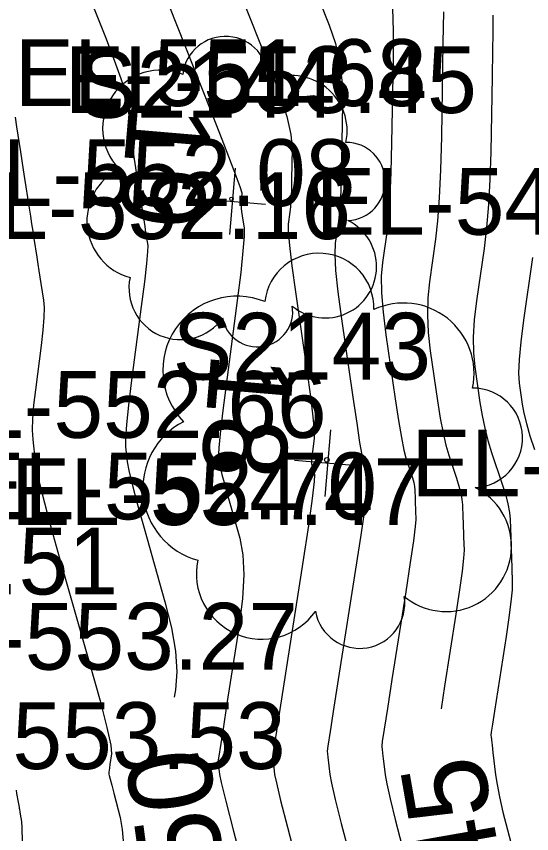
# Model space of a CAD drawing. Extents: x 1724534 to 1727318, y 657156 to 660047.
# Drawn here: x 1725483.91 to 1725514.76, y 658941.32 to 658990.26 of the extents above; entities that cross this region are included whole.
import ezdxf

# ---------------------------------------------------------------- set-up
doc = ezdxf.new("R2010")
doc.units = 0
for name, color, linetype in [('SURVEY - CENTERLINE - Preliminary', 7, 'Continuous'), ('SURVEY - CONTOURS - Index with Text', 7, 'Continuous'), ('SURVEY - CONTOURS - Intermediate with optional Text', 7, 'Continuous'), ('SURVEY - ROADSIDE BARRIERS - Points - Elevations', 7, 'Continuous'), ('SURVEY - TRAFFIC CONTROL - Pavement Marking - Points - Elevations', 7, 'Continuous'), ('SURVEY - TRANSPORTATION - Features - Points - Elevations', 7, 'Continuous'), ('SURVEY - TRANSPORTATION - Roads - Points - Elevations', 7, 'Continuous'), ('SURVEY - VEGETATION - Features - Points - Elevations', 7, 'Continuous'), ('SURVEY - VEGETATION - Features - Points - Locators', 7, 'Continuous'), ('SURVEY - VEGETATION - Features - Points - Numbers', 7, 'Continuous'), ('SURVEY - VEGETATION - Features with Text', 7, 'Continuous')]:
    doc.layers.add(name, color=color, linetype=linetype)

msp = doc.modelspace()

# ---------------------------------------------------------------- linework, layer by layer
at = {"layer": 'SURVEY - CENTERLINE - Preliminary'}
msp.add_arc((1727061.077, 658773.081), 1600, 165.79242, 172.785391, dxfattribs=at)
msp.add_arc((1727061.077, 658773.081), 1600, 165.79242, 172.785391, dxfattribs=at)
msp.add_arc((1727061.077, 658773.081), 1600, 165.79242, 172.785391, dxfattribs=at)
at = {"layer": 'SURVEY - CONTOURS - Index with Text'}
for points in [[(1725487.622, 658993.087), (1725489.235, 658989.013), (1725489.77, 658987.633), (1725490.164, 658986.548), (1725490.417, 658985.758), (1725490.53, 658985.263), (1725490.643, 658984.336), (1725490.684, 658983.995), (1725490.724, 658983.669), (1725490.763, 658983.355), (1725490.799, 658983.056), (1725490.895, 658982.275), (1725490.931, 658981.988), (1725490.968, 658981.71), (1725491.006, 658981.443), (1725491.045, 658981.186), (1725491.15, 658980.513), (1725491.188, 658980.266), (1725491.226, 658980.027), (1725491.262, 658979.797), (1725491.296, 658979.575), (1725491.386, 658978.997), (1725491.42, 658978.784), (1725491.452, 658978.578), (1725491.483, 658978.378), (1725491.513, 658978.186), (1725491.591, 658977.684), (1725491.62, 658977.498), (1725491.648, 658977.318), (1725491.675, 658977.144), (1725491.701, 658976.976), (1725491.77, 658976.535), (1725491.766, 658976.183), (1725491.701, 658975.459), (1725491.575, 658974.361), (1725491.389, 658972.89), (1725490.811, 658968.471), (1725490.626, 658966.979), (1725490.504, 658965.816), (1725490.446, 658964.983), (1725490.45, 658964.479), (1725490.545, 658963.575), (1725490.635, 658963.072), (1725490.833, 658962.243), (1725491.139, 658961.086), (1725491.554, 658959.602), (1725492.803, 658955.209), (1725493.193, 658953.644), (1725493.428, 658952.242), (1725493.507, 658951.005), (1725493.43, 658949.933), (1725493.362, 658949.5)], [(1725509.486, 658990.526), (1725509.454, 658988.673), (1725509.356, 658983.039), (1725509.306, 658981.071), (1725509.232, 658979.393), (1725509.133, 658978.006), (1725509.009, 658976.908), (1725508.644, 658974.369), (1725508.545, 658973.396), (1725508.521, 658972.381), (1725508.571, 658971.325), (1725508.696, 658970.228), (1725509.13, 658967.246), (1725509.294, 658966.203), (1725509.46, 658965.312), (1725509.629, 658964.572), (1725509.8, 658963.983), (1725510.258, 658962.614), (1725510.409, 658962.128), (1725510.52, 658961.699), (1725510.591, 658961.327), (1725510.621, 658961.011), (1725510.647, 658960.243), (1725510.657, 658959.954), (1725510.667, 658959.663), (1725510.677, 658959.37), (1725510.687, 658959.074), (1725510.713, 658958.285), (1725510.691, 658957.824), (1725510.602, 658957.033), (1725510.448, 658955.912), (1725510.229, 658954.46), (1725509.555, 658950.151), (1725509.343, 658948.791)]]:
    msp.add_lwpolyline(points, dxfattribs=at)
at = {"layer": 'SURVEY - CONTOURS - Intermediate with optional Text'}
for points in [[(1725501.52, 658992.574), (1725502.644, 658989.734), (1725503.01, 658988.641), (1725503.265, 658987.491), (1725503.409, 658986.284), (1725503.442, 658985.02), (1725503.382, 658981.574), (1725503.354, 658980.381), (1725503.313, 658979.387), (1725503.26, 658978.592), (1725503.195, 658977.995), (1725503.004, 658976.668), (1725502.974, 658976.013), (1725503.025, 658975.042), (1725503.158, 658973.756), (1725503.373, 658972.155), (1725504.056, 658967.464), (1725504.286, 658965.906), (1725504.465, 658964.75), (1725504.593, 658963.997), (1725504.668, 658963.646), (1725504.802, 658963.247), (1725504.846, 658963.106), (1725504.879, 658962.981), (1725504.899, 658962.872), (1725504.908, 658962.78), (1725504.918, 658962.472), (1725504.921, 658962.387), (1725504.927, 658962.215), (1725504.935, 658961.985), (1725504.892, 658961.618), (1725504.757, 658960.691), (1725504.531, 658959.201), (1725504.212, 658957.151), (1725503.241, 658950.936), (1725502.923, 658948.896), (1725502.696, 658947.437), (1725502.559, 658946.56), (1725502.514, 658946.264), (1725502.534, 658946.093), (1725502.557, 658945.906), (1725502.68, 658944.856), (1725502.779, 658944.334), (1725503.007, 658943.358), (1725503.364, 658941.93), (1725503.85, 658940.05)], [(1725497.279, 658991.755), (1725499.089, 658987.184), (1725499.681, 658985.596), (1725500.101, 658984.262), (1725500.348, 658983.181), (1725500.422, 658982.352), (1725500.39, 658980.481), (1725500.374, 658979.834), (1725500.352, 658979.294), (1725500.323, 658978.862), (1725500.288, 658978.538), (1725500.184, 658977.817), (1725500.182, 658977.361), (1725500.254, 658976.532), (1725500.4, 658975.33), (1725500.619, 658973.756), (1725501.302, 658969.062), (1725501.522, 658967.486), (1725501.668, 658966.278), (1725501.741, 658965.44), (1725501.74, 658964.971), (1725501.641, 658964.212), (1725501.609, 658963.959), (1725501.587, 658963.771), (1725501.575, 658963.647), (1725501.573, 658963.587), (1725501.58, 658963.513), (1725501.588, 658963.473), (1725501.604, 658963.405), (1725501.629, 658963.311), (1725501.662, 658963.19), (1725501.764, 658962.833), (1725501.749, 658962.405), (1725501.626, 658961.386), (1725501.397, 658959.779), (1725501.061, 658957.582), (1725500.023, 658950.937), (1725499.683, 658948.756), (1725499.44, 658947.197), (1725499.294, 658946.26), (1725499.246, 658945.944), (1725499.247, 658945.933), (1725499.251, 658945.901), (1725499.261, 658945.813), (1725499.278, 658945.669), (1725499.301, 658945.47), (1725499.373, 658944.863), (1725499.476, 658944.36), (1725499.73, 658943.307), (1725500.137, 658941.703), (1725500.695, 658939.549)], [(1725493.039, 658990.936), (1725495.534, 658984.633), (1725496.353, 658982.552), (1725496.937, 658981.033), (1725497.287, 658980.077), (1725497.402, 658979.685), (1725497.397, 658979.388), (1725497.394, 658979.286), (1725497.386, 658979.132), (1725497.381, 658979.081), (1725497.364, 658978.967), (1725497.364, 658978.895), (1725497.375, 658978.763), (1725497.398, 658978.573), (1725497.433, 658978.324), (1725497.541, 658977.581), (1725497.546, 658977.101), (1725497.478, 658976.217), (1725497.339, 658974.929), (1725497.127, 658973.237), (1725496.467, 658968.187), (1725496.253, 658966.507), (1725496.106, 658965.255), (1725496.025, 658964.43), (1725496.011, 658964.033), (1725496.063, 658963.544), (1725496.111, 658963.273), (1725496.219, 658962.824), (1725496.384, 658962.199), (1725496.608, 658961.396), (1725497.283, 658959.021), (1725497.471, 658958.024), (1725497.527, 658956.814), (1725497.452, 658955.392), (1725497.246, 658953.757), (1725496.52, 658949.114), (1725496.282, 658947.59), (1725496.01, 658945.845), (1725495.977, 658945.625), (1725495.978, 658945.617), (1725495.98, 658945.595), (1725495.988, 658945.533), (1725496.066, 658944.869), (1725496.172, 658944.386), (1725496.453, 658943.255), (1725496.909, 658941.476), (1725497.54, 658939.048)], [(1725506.43, 658990.72), (1725506.471, 658989.388), (1725506.463, 658987.688), (1725506.375, 658982.667), (1725506.334, 658980.929), (1725506.274, 658979.48), (1725506.197, 658978.321), (1725506.102, 658977.452), (1725505.824, 658975.518), (1725505.759, 658974.704), (1725505.773, 658973.712), (1725505.865, 658972.541), (1725506.035, 658971.191), (1725506.593, 658967.355), (1725506.79, 658966.055), (1725506.963, 658965.031), (1725507.111, 658964.284), (1725507.234, 658963.815), (1725507.53, 658962.93), (1725507.628, 658962.617), (1725507.699, 658962.34), (1725507.745, 658962.1), (1725507.764, 658961.895), (1725507.781, 658961.399), (1725507.788, 658961.213), (1725507.794, 658961.025), (1725507.8, 658960.835), (1725507.807, 658960.645), (1725507.824, 658960.135), (1725507.791, 658959.721), (1725507.68, 658958.862), (1725507.489, 658957.557), (1725507.221, 658955.806), (1725506.398, 658950.543), (1725506.129, 658948.816), (1725505.936, 658947.58), (1725505.821, 658946.836), (1725505.783, 658946.583), (1725505.785, 658946.565), (1725505.791, 658946.514), (1725505.808, 658946.373), (1725505.835, 658946.142), (1725505.873, 658945.822), (1725505.987, 658944.85), (1725506.083, 658944.307), (1725506.285, 658943.41), (1725506.592, 658942.158), (1725507.005, 658940.55)], [(1725512.443, 658990.332), (1725512.443, 658990.004), (1725512.435, 658989.283), (1725512.418, 658988.17), (1725512.393, 658986.665), (1725512.314, 658982.128), (1725512.267, 658980.491), (1725512.185, 658978.986), (1725512.068, 658977.61), (1725511.916, 658976.365), (1725511.464, 658973.22), (1725511.331, 658972.088), (1725511.268, 658971.051), (1725511.277, 658970.11), (1725511.358, 658969.265), (1725511.667, 658967.137), (1725511.798, 658966.352), (1725511.958, 658965.593), (1725512.147, 658964.859), (1725512.365, 658964.151), (1725512.986, 658962.297), (1725513.191, 658961.64), (1725513.341, 658961.059), (1725513.437, 658960.554), (1725513.477, 658960.126), (1725513.513, 658959.086), (1725513.526, 658958.695), (1725513.539, 658958.3), (1725513.553, 658957.904), (1725513.603, 658956.435), (1725513.59, 658955.927), (1725513.525, 658955.204), (1725513.407, 658954.267), (1725513.237, 658953.115), (1725512.54, 658948.655), (1725512.418, 658947.865), (1725512.345, 658947.387), (1725512.321, 658947.222), (1725512.324, 658947.197), (1725512.332, 658947.126), (1725512.355, 658946.932), (1725512.392, 658946.615), (1725512.444, 658946.175), (1725512.602, 658944.837), (1725512.69, 658944.255), (1725512.839, 658943.514), (1725513.047, 658942.612), (1725513.315, 658941.551), (1725514.109, 658938.509)], [(1725483.829, 658984.226), (1725483.915, 658983.652), (1725484.149, 658982.152), (1725484.236, 658981.599), (1725484.319, 658981.066), (1725484.399, 658980.552), (1725484.476, 658980.059), (1725484.677, 658978.768), (1725484.751, 658978.292), (1725484.823, 658977.832), (1725484.893, 658977.388), (1725484.959, 658976.959), (1725485.134, 658975.837), (1725485.199, 658975.423), (1725485.262, 658975.022), (1725485.322, 658974.634), (1725485.381, 658974.258), (1725485.534, 658973.274), (1725485.568, 658972.827), (1725485.556, 658972.224), (1725485.496, 658971.465), (1725485.39, 658970.55), (1725485.044, 658967.901), (1725484.937, 658966.97), (1725484.875, 658966.164), (1725484.859, 658965.482), (1725484.889, 658964.925), (1725485.028, 658963.606), (1725485.159, 658962.872), (1725485.448, 658961.662), (1725485.895, 658959.973), (1725486.499, 658957.808), (1725488.322, 658951.397), (1725488.916, 658949.263), (1725489.329, 658947.671), (1725489.562, 658946.619), (1725489.614, 658946.108), (1725489.514, 658945.468), (1725489.481, 658945.257), (1725489.458, 658945.107), (1725489.444, 658945.017), (1725489.439, 658944.986), (1725489.439, 658944.985), (1725489.441, 658944.974), (1725489.442, 658944.96), (1725489.451, 658944.882), (1725489.471, 658944.795), (1725489.526, 658944.577), (1725489.616, 658944.228), (1725489.741, 658943.748), (1725490.121, 658942.294), (1725490.249, 658941.558), (1725490.348, 658940.439)], [(1725514.823, 658975.822), (1725514.284, 658972.07), (1725514.116, 658970.779), (1725514.016, 658969.721), (1725513.984, 658968.895), (1725514.019, 658968.301), (1725514.205, 658967.028), (1725514.302, 658966.501), (1725514.456, 658965.873), (1725514.665, 658965.146), (1725514.931, 658964.319)], [(1725483.889, 658943.916), (1725483.925, 658943.717), (1725484.018, 658943.198), (1725484.07, 658942.906), (1725484.084, 658942.832), (1725484.088, 658942.808), (1725484.088, 658942.807), (1725484.091, 658942.786), (1725484.118, 658942.624), (1725484.141, 658942.483), (1725484.211, 658942.052), (1725484.238, 658941.672), (1725484.264, 658940.857)]]:
    msp.add_lwpolyline(points, dxfattribs=at)
at = {"layer": 'SURVEY - VEGETATION - Features - Points - Locators'}
for p, q in [((1725497.003, 658981.176), (1725496.665, 658977.19)), ((1725494.841, 658979.352), (1725498.827, 658979.014)), ((1725502.726, 658965.501), (1725502.388, 658961.515)), ((1725500.564, 658963.677), (1725504.55, 658963.339))]:
    msp.add_line(p, q, dxfattribs=at)
at = {"layer": 'SURVEY - VEGETATION - Features with Text'}
for centre, radius in [((1725496.79, 658979.332), 0.108), ((1725502.501, 658963.697), 0.137)]:
    msp.add_circle(centre, radius, dxfattribs=at)
for centre, radius, start, end in [((1725496.426, 658986.484), 2.575, 358.2631, 173.2634), ((1725492.562, 658983.549), 3.491, 68.0102, 223.8487), ((1725500.399, 658983.397), 3.318, 348.1042, 114.9499), ((1725503.652, 658980.371), 2.342, 272.8171, 90.1363), ((1725491.646, 658978.003), 3.514, 117.1144, 254.6386), ((1725502.399, 658975.275), 3.077, 230.1985, 63.6182), ((1725502.038, 658972.8), 3.277, 358.2631, 173.2634), ((1725493.733, 658973.984), 3.084, 168.0616, 324.8506), ((1725497.12, 658969.064), 4.443, 68.0102, 223.8487), ((1725498.338, 658972.583), 2.117, 190.1778, 8.9234), ((1725507.094, 658968.872), 4.223, 348.1042, 114.9499), ((1725511.234, 658965.02), 2.981, 272.8171, 90.1363), ((1725495.954, 658962.006), 4.472, 117.1144, 254.6386), ((1725509.64, 658958.535), 3.917, 230.1985, 63.6182), ((1725498.61, 658956.891), 3.925, 168.0616, 324.8506), ((1725504.471, 658955.108), 2.694, 190.1778, 8.9234)]:
    msp.add_arc(centre, radius, start, end, dxfattribs=at)

# ---------------------------------------------------------------- texts
at = {"layer": 'SURVEY - CONTOURS - Index with Text'}
for s, rotation, p in [('550', 97.7093, (1725496.858, 658935.592)), ('545', 99.9398, (1725513.691, 658935.217))]:
    msp.add_text(s, height=5, rotation=rotation, dxfattribs=at).set_placement(p)
at = {"layer": 'SURVEY - ROADSIDE BARRIERS - Points - Elevations'}
for s, p in [('EL-553.45', (1725486.795, 658984.471)), ('EL-554.47', (1725483.578, 658959.799))]:
    msp.add_text(s, height=4, dxfattribs=at).set_placement(p)
at = {"layer": 'SURVEY - TRAFFIC CONTROL - Pavement Marking - Points - Elevations'}
msp.add_text('EL-553.51', height=4, dxfattribs=at).set_placement((1725465.313, 658955.642))
at = {"layer": 'SURVEY - TRANSPORTATION - Features - Points - Elevations'}
for s, p in [('EL-551.68', (1725483.797, 658984.889)), ('EL-552.70', (1725480.825, 658960.14))]:
    msp.add_text(s, height=4, dxfattribs=at).set_placement(p)
at = {"layer": 'SURVEY - TRANSPORTATION - Roads - Points - Elevations'}
for s, p in [('EL-552.08', (1725479.526, 658978.901)), ('EL-552.16', (1725479.261, 658976.921)), ('EL-552.66', (1725477.804, 658965.02)), ('EL-553.27', (1725476.086, 658951.138)), ('EL-553.53', (1725475.348, 658945.189))]:
    msp.add_text(s, height=4, dxfattribs=at).set_placement(p)
at = {"layer": 'SURVEY - VEGETATION - Features - Points - Elevations'}
for s, p in [('EL-549.19', (1725501.834, 658977.183)), ('EL-547.82', (1725507.557, 658961.508))]:
    msp.add_text(s, height=4, dxfattribs=at).set_placement(p)
at = {"layer": 'SURVEY - VEGETATION - Features - Points - Numbers'}
for s, p in [('S2144', (1725487.546, 658984.183)), ('S2143', (1725493.269, 658968.508))]:
    msp.add_text(s, height=4, dxfattribs=at).set_placement(p)
at = {"layer": 'SURVEY - VEGETATION - Features with Text'}
for s, p in [('19', (1725490.679, 658985.19)), ('18', (1725495.592, 658970.223))]:
    msp.add_text(s, height=5, rotation=265.1461, dxfattribs=at).set_placement(p)

doc.saveas('drawing.dxf')
